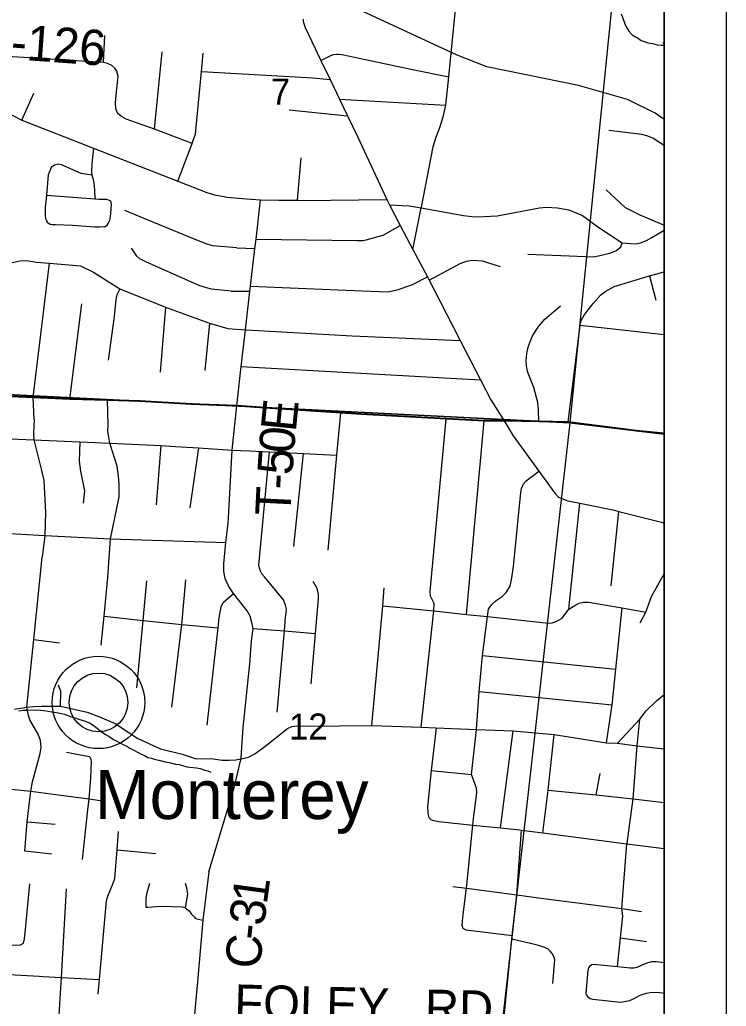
# Model space of a CAD drawing. Extents: x 0 to 43.4, y -8.1 to 22.
# Drawn here: x 7.863 to 9, y 16.255 to 17.842 of the extents above; entities that cross this region are included whole.
import ezdxf

# ---------------------------------------------------------------- set-up
doc = ezdxf.new("R2010")
doc.units = 0
for name, color, linetype in [('GM_X_City_Street', 7, 'Continuous'), ('GM_X_Corporation', 7, 'Continuous'), ('GM_X_County_Road', 7, 'Continuous'), ('GM_X_County_Road_Text', 7, 'Continuous'), ('GM_X_Minor_River', 7, 'Continuous'), ('GM_X_Rail_Line', 7, 'Continuous'), ('GM_X_Section_Text', 7, 'Continuous'), ('GM_X_State_Route', 7, 'Continuous'), ('GM_X_Township_Road', 7, 'Continuous'), ('GM_X_Township_Road_Text', 7, 'Continuous'), ('GM_X_Unincorporated', 7, 'Continuous'), ('GM_X_Unincorporated_Location', 7, 'Continuous'), ('GM_X_Unincorporated_Text', 7, 'Continuous'), ('SH_Data', 7, 'Continuous')]:
    doc.layers.add(name, color=color, linetype=linetype)

msp = doc.modelspace()

# ---------------------------------------------------------------- linework, layer by layer
at = {"layer": 'GM_X_City_Street'}
for p, q in [((8.8978, 17.8048), (8.9, 17.8046)), ((8.3349, 17.7485), (8.3626, 17.7457)), ((8.3778, 17.714), (8.549, 17.7043)), ((8.297, 17.6971), (8.3907, 17.6872)), ((8.3101, 17.5513), (8.3161, 17.6194)), ((8.2124, 17.475), (8.2416, 17.4738)), ((8.8763, 17.4296), (8.8869, 17.3908)), ((8.2037, 17.4054), (8.2337, 17.4052)), ((8.7652, 17.3507), (8.9, 17.3355)), ((8.2197, 17.2841), (8.6047, 17.2626)), ((8.5819, 16.8853), (8.6105, 17.1967)), ((8.0902, 17.1567), (8.0827, 17.0615)), ((8.3041, 16.9943), (8.3196, 17.1438)), ((8.7465, 16.8937), (8.7646, 17.0639)), ((8.8147, 16.9312), (8.8269, 17.0509)), ((8.6079, 16.8193), (8.8222, 16.7971)), ((8.6025, 16.7611), (8.8164, 16.7397)), ((8.5253, 16.6339), (8.5903, 16.6275)), ((8.7905, 16.5952), (8.797, 16.6291)), ((8.8296, 16.3648), (8.8715, 16.3588))]:
    msp.add_line(p, q, dxfattribs=at)
for points in [[(8.3479, 17.7763), (8.3638, 17.784), (8.3683, 17.7859), (8.3727, 17.7864), (8.3763, 17.7866), (8.3813, 17.7858), (8.4119, 17.7796), (8.4953, 17.7619), (8.5535, 17.7498)], [(8.9, 17.6392), (8.8928, 17.6443), (8.882, 17.6511), (8.8723, 17.655), (8.864, 17.6573), (8.8109, 17.6634)], [(8.8067, 17.5683), (8.8376, 17.5396), (8.861, 17.5282), (8.9, 17.5115)], [(8.4582, 17.544), (8.4897, 17.5425), (8.5091, 17.539), (8.5773, 17.5267), (8.5954, 17.5246), (8.6098, 17.5252), (8.6315, 17.5264), (8.6997, 17.5394), (8.711, 17.5403), (8.7283, 17.5391), (8.7467, 17.5359), (8.7685, 17.5267), (8.7949, 17.5076), (8.8324, 17.4828)], [(8.2434, 17.4886), (8.4064, 17.4865), (8.4158, 17.4866), (8.4206, 17.4875), (8.4338, 17.4913), (8.4479, 17.495), (8.4756, 17.5108)], [(8.6809, 17.4647), (8.7869, 17.4605), (8.8038, 17.464), (8.8142, 17.467), (8.8235, 17.4708), (8.8302, 17.4767), (8.8324, 17.4828), (8.8464, 17.482), (8.8545, 17.4815), (8.8621, 17.4827), (8.8718, 17.4869), (8.8801, 17.4915), (8.9, 17.5031)], [(8.5219, 17.4227), (8.5717, 17.4497), (8.5821, 17.4536), (8.5918, 17.4551), (8.6071, 17.4537), (8.6362, 17.445)], [(8.2346, 17.413), (8.4138, 17.4057), (8.4556, 17.404), (8.4705, 17.4073), (8.4939, 17.4153), (8.5191, 17.4282)], [(8.7457, 17.1943), (8.7652, 17.3507), (8.7665, 17.3577), (8.7713, 17.3665), (8.7776, 17.3753), (8.7859, 17.3853), (8.7983, 17.3993), (8.8062, 17.4051), (8.8196, 17.4124), (8.8763, 17.4296), (8.9, 17.4364)], [(8.6984, 17.1954), (8.6981, 17.2135), (8.6969, 17.2262), (8.6903, 17.2501), (8.6803, 17.2759), (8.6788, 17.2848), (8.6783, 17.2929), (8.6787, 17.3002), (8.6796, 17.3084), (8.6819, 17.3168), (8.6852, 17.3253), (8.6885, 17.3333), (8.6987, 17.3491), (8.7081, 17.3599), (8.7331, 17.3813)], [(8.1979, 17.3449), (8.2265, 17.3432), (8.2283, 17.3431), (8.3983, 17.3331), (8.5721, 17.326)], [(8.3596, 16.9884), (8.3736, 17.1411), (8.3798, 17.2094)], [(7.8867, 17.1991), (7.8855, 17.1757), (7.8862, 17.1659), (7.8925, 17.1405), (7.8983, 17.1165), (7.9021, 17.1005), (7.9045, 17.0496), (7.9034, 17.012), (7.8996, 16.9771)], [(7.9944, 16.8359), (7.9991, 16.8821), (8.005, 16.9445), (8.0093, 17.0069), (8.023, 17.0744), (8.0232, 17.0874), (8.0232, 17.0951), (8.0222, 17.1073), (8.0198, 17.1236), (8.0085, 17.1604), (8.0059, 17.1734), (8.005, 17.1794), (8.0053, 17.1899)], [(8.5091, 16.7036), (8.5295, 16.8907), (8.5298, 16.9028), (8.5242, 16.9144), (8.5235, 16.9218), (8.5491, 17.2)], [(7.7363, 17.1725), (7.7606, 17.1712), (7.8358, 17.1679), (7.8862, 17.1659), (7.9601, 17.1629), (8.0085, 17.1604), (8.0902, 17.1567), (8.1141, 17.1554)], [(7.9601, 17.1629), (7.9588, 17.1315), (7.9612, 17.1154), (7.9674, 17.084), (7.9655, 17.0641)], [(8.2332, 17.1481), (8.2651, 17.1465), (8.3196, 17.1438), (8.3736, 17.1411)], [(8.2776, 16.728), (8.289, 16.8589), (8.2909, 16.8809), (8.2919, 16.8871), (8.2922, 16.8935), (8.2908, 16.9), (8.2877, 16.9087), (8.257, 16.9454), (8.253, 16.9503), (8.2508, 16.9545), (8.2489, 16.9594), (8.248, 16.9646), (8.2651, 17.1465)], [(7.7811, 17.0191), (7.9034, 17.012), (8.0093, 17.0069), (8.1949, 17.0006)], [(8.8614, 16.8716), (8.8705, 16.889), (8.8798, 16.9142), (8.9, 16.9503)], [(8.0515, 16.7672), (8.0621, 16.8754), (8.068, 16.9392)], [(8.1078, 16.736), (8.1242, 16.8691), (8.1306, 16.9406)], [(8.332, 16.7733), (8.3393, 16.8546), (8.3442, 16.9101), (8.344, 16.9175), (8.3417, 16.9271), (8.3356, 16.938)], [(8.1646, 16.7068), (8.1827, 16.8637), (8.1843, 16.8799), (8.1871, 16.8971), (8.1908, 16.9046), (8.2073, 16.9189)], [(8.4299, 16.7063), (8.4474, 16.8992), (8.4495, 16.928)], [(8.6161, 16.882), (8.7139, 16.8711), (8.72, 16.8718), (8.7262, 16.8738), (8.7359, 16.8791), (8.7465, 16.8937), (8.7565, 16.8996), (8.7633, 16.9034), (8.7705, 16.9051), (8.7786, 16.9048), (8.8323, 16.8956), (8.8705, 16.889)], [(8.4474, 16.8992), (8.5295, 16.8907), (8.5819, 16.8853), (8.6161, 16.882)], [(8.8072, 16.6788), (8.8164, 16.7397), (8.8222, 16.7971), (8.8323, 16.8956)], [(7.9991, 16.8821), (8.0621, 16.8754), (8.1242, 16.8691), (8.1827, 16.8637)], [(8.2387, 16.8627), (8.289, 16.8589), (8.3393, 16.8546)], [(8.8249, 16.319), (8.8296, 16.3648), (8.8338, 16.3998), (8.8322, 16.4122), (8.8402, 16.5161), (8.8403, 16.5171), (8.8501, 16.5885), (8.8565, 16.6737), (8.8609, 16.7168)], [(8.637, 16.5417), (8.6404, 16.5708), (8.6571, 16.6978)], [(8.7049, 16.5337), (8.7136, 16.6024), (8.723, 16.692)], [(8.825, 16.6778), (8.8565, 16.6737), (8.9, 16.6689)], [(8.7136, 16.6024), (8.7905, 16.5952), (8.8501, 16.5885), (8.9, 16.5826)], [(8.6555, 16.3679), (8.5814, 16.3772), (8.5766, 16.38), (8.575, 16.3848), (8.5764, 16.3984), (8.5822, 16.4446), (8.592, 16.5463)], [(8.5603, 16.4476), (8.5822, 16.4446), (8.663, 16.4343), (8.7062, 16.4284), (8.8322, 16.4122), (8.8636, 16.4072)], [(8.7207, 16.2916), (8.724, 16.3297), (8.7226, 16.3351), (8.72, 16.3398), (8.7167, 16.3436), (8.7134, 16.3466), (8.7079, 16.3495), (8.7019, 16.3513), (8.694, 16.3535), (8.6551, 16.3629)], [(8.7753, 16.2728), (8.7745, 16.2761), (8.7777, 16.3131), (8.7788, 16.3168), (8.7799, 16.3185), (8.7815, 16.3204), (8.7838, 16.3218), (8.7862, 16.3225), (8.8249, 16.319), (8.8454, 16.3165), (8.8512, 16.3169), (8.8567, 16.3179), (8.8683, 16.323), (8.8745, 16.3254), (8.88, 16.3266), (8.8873, 16.327), (8.9, 16.3251)], [(8.7753, 16.2728), (8.7775, 16.27), (8.7808, 16.2675), (8.7851, 16.2664), (8.8299, 16.2616), (8.8387, 16.2629), (8.8443, 16.2643), (8.8519, 16.2674), (8.8606, 16.2721), (8.8662, 16.2742), (8.8716, 16.2758), (8.8777, 16.2772), (8.8876, 16.2777), (8.8972, 16.2766), (8.9, 16.2761)]]:
    msp.add_lwpolyline(points, dxfattribs=at)
at = {"layer": 'GM_X_Corporation'}
for points in [[(8.9, 14.3814), (8.9, 20.9), (2.1, 20.9)], [(7.7999, 17.2384), (7.8847, 17.2346), (7.9436, 17.232), (8.0041, 17.2301), (8.0564, 17.2286), (8.139, 17.2237), (8.2121, 17.2213), (8.3796, 17.21), (8.4125, 17.2077), (8.5489, 17.2005), (8.6103, 17.1972), (8.6426, 17.1973), (8.6981, 17.1959), (8.7454, 17.1948), (8.8548, 17.1812), (8.9, 17.1765), (8.9, 20.9)], [(8.9, 14.3814), (8.9, 17.1765), (8.8548, 17.1812), (8.7454, 17.1948), (8.6981, 17.1959), (8.6426, 17.1973), (8.6103, 17.1972), (8.5489, 17.2005), (8.4125, 17.2077), (8.3796, 17.21), (8.2121, 17.2213), (8.139, 17.2237), (8.0564, 17.2286), (8.0041, 17.2301), (7.9436, 17.232), (7.8847, 17.2346), (7.7999, 17.2384)]]:
    msp.add_lwpolyline(points, dxfattribs=at)
for points in [[(8.8482, 18.1867), (8.7485, 17.1931), (7.7575, 17.2431), (7.8526, 18.2674)], [(8.9, 17.1752), (8.9, 18.1813), (8.8482, 18.1867), (8.7485, 17.1931)], [(7.7575, 17.2431), (8.7485, 17.1931), (8.6363, 16.199), (7.6501, 16.228)], [(8.9, 16.1667), (8.9, 17.1752), (8.7485, 17.1931), (8.6363, 16.199)]]:
    msp.add_lwpolyline(points, close=True, dxfattribs=at)
at = {"layer": 'GM_X_County_Road'}
for p, q in [((8.2507, 17.5519), (8.2804, 17.5516)), ((8.4959, 17.4722), (8.5091, 17.539)), ((8.1491, 16.294), (8.1419, 16.2128))]:
    msp.add_line(p, q, dxfattribs=at)
for points in [[(8.5091, 17.539), (8.5094, 17.5405), (8.5284, 17.6371), (8.5329, 17.6519), (8.5389, 17.6682), (8.5445, 17.6856), (8.549, 17.7043), (8.5535, 17.7498), (8.5802, 18.0214), (8.5891, 18.1119), (8.5951, 18.1657), (8.6156, 18.3483)], [(7.6994, 17.7637), (7.7646, 17.7326), (7.8665, 17.6802), (7.9818, 17.6351), (8.1177, 17.5819), (8.1642, 17.5637), (8.1766, 17.56), (8.1924, 17.5572)], [(8.1924, 17.5572), (8.1944, 17.5568), (8.1966, 17.5564), (8.2282, 17.5538), (8.2507, 17.5519)], [(8.2804, 17.5516), (8.3101, 17.5513), (8.3179, 17.5512), (8.4537, 17.5525)], [(6.2065, 17.4049), (6.4191, 17.3852), (6.5024, 17.3775), (6.7305, 17.3523), (6.8403, 17.3405), (6.934, 17.3317), (7.0194, 17.3221), (7.1459, 17.3085), (7.2379, 17.2981), (7.3491, 17.2862), (7.3995, 17.281), (7.6127, 17.2515), (7.6512, 17.2473), (7.707, 17.2463), (7.7489, 17.2401), (7.8001, 17.2378), (7.885, 17.2341), (7.9438, 17.2315), (8.0044, 17.2296), (8.0566, 17.228), (8.1392, 17.2232), (8.1943, 17.2214)], [(8.1943, 17.2214), (8.2123, 17.2208), (8.2419, 17.2188)], [(8.2419, 17.2188), (8.3798, 17.2094), (8.4127, 17.2072), (8.5491, 17.2), (8.6105, 17.1967), (8.6429, 17.1968)], [(8.6429, 17.1968), (8.6984, 17.1954), (8.7362, 17.1945)], [(8.7362, 17.1945), (8.7457, 17.1943), (8.855, 17.1807), (8.9, 17.176)], [(8.592, 16.5463), (8.5933, 16.5569), (8.5985, 16.5984), (8.5979, 16.6056), (8.5903, 16.6275), (8.5981, 16.6999), (8.6025, 16.7611), (8.6079, 16.8193), (8.6161, 16.882), (8.6177, 16.8937), (8.6222, 16.9004), (8.6298, 16.9074), (8.6392, 16.9139), (8.6461, 16.9206), (8.6523, 16.9307), (8.655, 16.9439), (8.6575, 16.962), (8.6695, 17.0814), (8.6705, 17.0877), (8.6738, 17.0953), (8.6782, 17.1), (8.6984, 17.1157)], [(8.1901, 16.6506), (8.2002, 16.6506), (8.2112, 16.6515), (8.2196, 16.6531), (8.2311, 16.6556), (8.2415, 16.6611), (8.2574, 16.6725), (8.2941, 16.7016), (8.301, 16.7048), (8.3087, 16.7062), (8.3249, 16.7053), (8.4299, 16.7063), (8.5091, 16.7036), (8.5335, 16.7025), (8.5981, 16.6999), (8.6571, 16.6978), (8.723, 16.692), (8.8072, 16.6788), (8.825, 16.6778), (8.8609, 16.7168), (8.8709, 16.7302), (8.8875, 16.7461), (8.9, 16.7565)], [(7.8546, 16.7325), (7.8749, 16.7361), (7.8859, 16.7369), (7.898, 16.7378), (7.9286, 16.7377), (7.972, 16.7277), (7.9918, 16.7202), (8.017, 16.7095), (8.0534, 16.6858), (8.0899, 16.6692), (8.1245, 16.6605), (8.1471, 16.6528), (8.1711, 16.6532), (8.1891, 16.6506), (8.1901, 16.6506)], [(8.5335, 16.7025), (8.5253, 16.6339), (8.5195, 16.5756), (8.5199, 16.567), (8.5201, 16.5659)], [(8.5201, 16.5659), (8.5205, 16.5628), (8.5217, 16.5586), (8.5234, 16.5566), (8.5247, 16.5554), (8.5271, 16.5543), (8.5295, 16.5535), (8.5321, 16.5529), (8.5375, 16.552), (8.592, 16.5463), (8.637, 16.5417), (8.6679, 16.5385), (8.6708, 16.5382)], [(8.639, 16.2005), (8.6551, 16.3629), (8.6555, 16.3679), (8.663, 16.4343), (8.6708, 16.5382)], [(8.6708, 16.5382), (8.7049, 16.5337), (8.8402, 16.5161), (8.9, 16.5084)], [(8.1673, 16.4711), (8.158, 16.3932), (8.1491, 16.294)]]:
    msp.add_lwpolyline(points, dxfattribs=at)
at = {"layer": 'GM_X_Minor_River'}
for points in [[(8.8309, 17.8513), (8.8331, 17.8459), (8.8373, 17.8336), (8.8402, 17.8289), (8.8435, 17.8235), (8.8483, 17.818), (8.8528, 17.8148), (8.8573, 17.8124), (8.8629, 17.8085), (8.8693, 17.8064), (8.8738, 17.8047), (8.8814, 17.8034), (8.8889, 17.8016), (8.8954, 17.8007), (8.9, 17.8006)], [(7.862, 16.73), (7.8688, 16.7309), (7.8738, 16.7312), (7.8883, 16.7315), (7.8974, 16.7309), (7.9057, 16.7299), (7.9148, 16.7285), (7.9258, 16.7267), (7.9345, 16.7245), (7.9394, 16.7229), (7.9476, 16.72), (7.9522, 16.7187), (7.9567, 16.717), (7.9684, 16.7137), (7.9755, 16.7108), (7.9815, 16.7072), (7.9879, 16.7021), (7.9945, 16.6966), (8.0013, 16.6918), (8.0069, 16.6886), (8.014, 16.6838), (8.0207, 16.6806), (8.0252, 16.6778), (8.0305, 16.6754), (8.0354, 16.673), (8.0402, 16.6698), (8.0459, 16.6673), (8.0519, 16.6641), (8.059, 16.6601), (8.0642, 16.6581), (8.0695, 16.6552), (8.0752, 16.6539), (8.0816, 16.6519), (8.0872, 16.6506), (8.0971, 16.648), (8.1039, 16.6467), (8.1141, 16.6445), (8.1198, 16.6439), (8.125, 16.6423), (8.1322, 16.6402), (8.1371, 16.6393), (8.1424, 16.6391), (8.1477, 16.6382), (8.1538, 16.6373), (8.1613, 16.6348), (8.1659, 16.6335), (8.1708, 16.6315)]]:
    msp.add_lwpolyline(points, dxfattribs=at)
at = {"layer": 'GM_X_Rail_Line'}
msp.add_lwpolyline([(8.9, 17.6811), (8.8855, 17.6915), (8.8412, 17.7137), (8.762, 17.7358), (8.6148, 17.7659), (8.5673, 17.785), (8.3852, 17.869)], dxfattribs=at)
at = {"layer": 'GM_X_State_Route'}
for points in [[(8.3195, 17.8426), (8.3192, 17.8388), (8.3225, 17.8291), (8.3387, 17.7953)], [(8.3387, 17.7953), (8.3419, 17.7887), (8.3479, 17.7763), (8.3626, 17.7457), (8.3778, 17.714), (8.3907, 17.6872), (8.4066, 17.6542), (8.4537, 17.5525), (8.4582, 17.544), (8.4756, 17.5108), (8.4959, 17.4722), (8.5191, 17.4282), (8.5219, 17.4227), (8.5398, 17.3887), (8.5721, 17.326), (8.6047, 17.2626), (8.6213, 17.2302), (8.6429, 17.1968), (8.657, 17.1724), (8.6984, 17.1157), (8.7243, 17.0802), (8.7299, 17.0737), (8.7451, 17.0678), (8.7646, 17.0639), (8.7749, 17.0618)], [(8.7749, 17.0618), (8.8203, 17.0526), (8.8269, 17.0509), (8.8957, 17.0333), (8.9, 17.0319)]]:
    msp.add_lwpolyline(points, dxfattribs=at)
at = {"layer": 'GM_X_Township_Road'}
for p, q in [((7.9981, 17.7728), (8.0003, 17.8165)), ((8.0803, 17.6655), (8.0926, 17.7903)), ((8.1557, 17.7586), (8.3349, 17.7485)), ((7.8665, 17.6802), (7.8862, 17.7237)), ((8.0789, 17.5158), (8.0326, 17.5347)), ((7.9438, 17.2315), (7.9633, 17.3847)), ((8.098, 17.3795), (8.089, 17.2749)), ((8.1686, 17.3535), (8.1609, 17.2776)), ((7.8867, 17.1991), (7.885, 17.2341)), ((8.0053, 17.1899), (8.0044, 17.2296)), ((8.151, 17.1531), (8.1372, 17.0564)), ((8.205, 17.1492), (8.2332, 17.1481)), ((7.886, 16.8446), (7.9272, 16.8394)), ((7.8753, 16.5515), (7.9201, 16.5477)), ((8.0198, 16.5067), (8.0824, 16.5008))]:
    msp.add_line(p, q, dxfattribs=at)
for points in [[(8.1406, 17.6429), (8.0803, 17.6655), (8.0346, 17.6817), (8.027, 17.6862), (8.0213, 17.6911), (8.018, 17.6987), (8.0173, 17.7086), (8.0182, 17.7204), (8.0215, 17.751), (8.0197, 17.7588), (8.0164, 17.7637), (8.0115, 17.7683), (8.0043, 17.7716), (7.9981, 17.7728), (7.8002, 17.7851), (7.7918, 17.7827), (7.7856, 17.7784), (7.7814, 17.7708), (7.7646, 17.7326), (7.7473, 17.6986), (7.7459, 17.6893), (7.7482, 17.6409), (7.7521, 17.5288)], [(8.1177, 17.5819), (8.1406, 17.6429), (8.1418, 17.6462), (8.1441, 17.6518), (8.1462, 17.6579), (8.1557, 17.7586), (8.1584, 17.7879)], [(7.9818, 17.6351), (7.9791, 17.6101), (7.9785, 17.5971), (7.9791, 17.5919), (7.9806, 17.5884), (7.9816, 17.585), (7.9826, 17.5789), (7.9837, 17.5683), (7.9841, 17.5536)], [(7.9791, 17.5919), (7.9619, 17.5946), (7.9306, 17.6086), (7.9254, 17.6092), (7.9191, 17.608), (7.9139, 17.6042), (7.9116, 17.5986), (7.9088, 17.5922), (7.9064, 17.5597), (7.9043, 17.5395), (7.904, 17.5323), (7.9044, 17.5275), (7.9048, 17.5218), (7.9061, 17.5187), (7.9074, 17.5163), (7.9103, 17.514)], [(7.9064, 17.5597), (7.9841, 17.5536), (7.9909, 17.5533), (7.997, 17.5533), (8.0009, 17.553), (8.0027, 17.5529), (8.0058, 17.5519), (8.0092, 17.5503)], [(8.2123, 17.2208), (8.2197, 17.2841), (8.2265, 17.3432), (8.2337, 17.4052), (8.2346, 17.413), (8.2416, 17.4738), (8.2434, 17.4886), (8.2507, 17.5519)], [(8.0092, 17.5503), (8.0105, 17.5445), (8.0093, 17.5304), (8.0088, 17.525), (8.0077, 17.5189), (8.0055, 17.5143), (8.0031, 17.5105), (8.0002, 17.5083), (7.9963, 17.5084), (7.9914, 17.5081), (7.9836, 17.5082)], [(7.9836, 17.5082), (7.9482, 17.5107), (7.9209, 17.5116), (7.9156, 17.512), (7.9123, 17.5125), (7.9103, 17.514)], [(8.2124, 17.475), (8.1734, 17.4783), (8.1633, 17.4812), (8.1483, 17.4873), (8.0789, 17.5158)], [(8.2037, 17.4054), (8.1719, 17.4081), (8.1637, 17.4103), (8.1532, 17.4136), (8.067, 17.452), (8.0563, 17.457), (8.0515, 17.4616), (8.0431, 17.4742)], [(7.8275, 17.4439), (7.8488, 17.4508), (7.8635, 17.4537), (7.874, 17.4547), (7.8902, 17.4519), (7.9114, 17.4501), (7.9611, 17.4457), (7.9817, 17.4356), (8.0242, 17.409), (8.098, 17.3795), (8.1686, 17.3535), (8.1979, 17.3449)], [(7.885, 17.2341), (7.8887, 17.2654), (7.9114, 17.4501)], [(8.0242, 17.409), (8.0195, 17.3991), (8.0177, 17.3919), (8.0153, 17.3645), (8.0053, 17.2942)], [(8.1984, 17.0322), (8.1993, 17.0406), (8.205, 17.1492), (8.2123, 17.2208)], [(8.1141, 17.1554), (8.151, 17.1531), (8.205, 17.1492)], [(8.2073, 16.9189), (8.1997, 16.9301), (8.194, 16.9429), (8.1916, 16.9542), (8.1917, 16.9663), (8.1949, 17.0006), (8.1984, 17.0322)], [(7.8749, 16.7361), (7.886, 16.8446), (7.8996, 16.9771)], [(8.2202, 16.6631), (8.2225, 16.7033), (8.2336, 16.8058), (8.2364, 16.8427), (8.2387, 16.8627), (8.236, 16.8742), (8.2338, 16.8821), (8.2294, 16.8912), (8.2073, 16.9189)], [(7.9286, 16.7377), (7.9293, 16.761), (7.9259, 16.7712)], [(7.9151, 16.4993), (7.8717, 16.5046), (7.8753, 16.5515), (7.8811, 16.6007), (7.8837, 16.616), (7.8964, 16.6614), (7.8977, 16.6712), (7.8967, 16.6825), (7.8929, 16.6926), (7.8796, 16.7157), (7.8774, 16.7224), (7.8749, 16.7361)], [(7.9645, 16.4907), (7.9731, 16.5706), (7.9748, 16.5883), (7.9779, 16.6217), (7.9785, 16.6498), (7.9782, 16.6516), (7.9774, 16.6542), (7.9763, 16.6556), (7.9754, 16.6563), (7.9384, 16.663)], [(8.1673, 16.4711), (8.2086, 16.6086), (8.2181, 16.6473), (8.2196, 16.6531), (8.2202, 16.6631)], [(7.8493, 16.6038), (7.8811, 16.6007), (7.9296, 16.5943), (7.9748, 16.5883), (7.9997, 16.585)], [(7.9895, 16.2741), (7.9916, 16.2979), (8.003, 16.4244), (8.0051, 16.4319), (8.0136, 16.4526), (8.0161, 16.4605), (8.0198, 16.5067), (8.0223, 16.5362)], [(7.8329, 16.4547), (7.8214, 16.3546), (7.8168, 16.3151), (7.8179, 16.3117), (7.8212, 16.3086), (7.8265, 16.3069), (7.8945, 16.3032), (7.9004, 16.3029)], [(7.8214, 16.3546), (7.853, 16.3531), (7.8644, 16.3539), (7.8696, 16.3565), (7.8707, 16.3632), (7.872, 16.3732), (7.8793, 16.4516)], [(7.9253, 16.2153), (7.9303, 16.3012), (7.9386, 16.4436)], [(8.0722, 16.4525), (8.0677, 16.4375), (8.0662, 16.4292), (8.0662, 16.4142), (8.0692, 16.4142), (8.091, 16.4157), (8.1248, 16.4149), (8.1274, 16.4142), (8.1299, 16.413), (8.1318, 16.4118), (8.1357, 16.4086), (8.1398, 16.4028), (8.1442, 16.3981), (8.1456, 16.3964), (8.1481, 16.3954), (8.158, 16.3932)], [(8.1299, 16.413), (8.1338, 16.4352), (8.1323, 16.445), (8.1301, 16.4525)], [(7.9004, 16.3029), (7.9303, 16.3012), (7.9916, 16.2979)]]:
    msp.add_lwpolyline(points, dxfattribs=at)
at = {"layer": 'GM_X_Unincorporated'}
for radius in [0.0744, 0.0472]:
    msp.add_circle((7.9899, 16.7437), radius, dxfattribs=at)
at = {"layer": 'GM_X_Unincorporated_Location'}
msp.add_line((7.9899, 16.7437), (7.9899, 16.7437), dxfattribs=at)
at = {"layer": 'SH_Data'}
for p, q in [((9, 21), (9, 14)), ((8.9, 20.9), (8.9, 14.1))]:
    msp.add_line(p, q, dxfattribs=at)

# ---------------------------------------------------------------- texts
at = {"layer": 'GM_X_County_Road_Text'}
for s, height, rotation, p in [('C-126', 0.05682, 355.8754, (7.7931, 17.7825)), ('1', 0.0568, 82.2195, (8.2607, 16.4175)), ('3', 0.0568, 83.1235, (8.2565, 16.383)), ('-', 0.0568, 84.0882, (8.2541, 16.36)), ('C', 0.0568, 85.1584, (8.2502, 16.3138)), ('FOLEY', 0.05682, 358.5154, (8.2079, 16.2333)), ('RD', 0.05682, 359.0128, (8.5147, 16.225))]:
    msp.add_text(s, height=height, rotation=rotation, dxfattribs=at).set_placement(p)
at = {"layer": 'GM_X_Section_Text'}
for s, height, p in [('7', 0.0419, (8.2673, 17.7053)), ('12', 0.04186, (8.2964, 16.6839))]:
    msp.add_text(s, height=height, rotation=0, dxfattribs=at).set_placement(p)
at = {"layer": 'GM_X_Township_Road_Text'}
for s, rotation, p in [('E', 84.2303, (8.3073, 17.1776)), ('0', 85.199, (8.3044, 17.143)), ('5', 86.107, (8.302, 17.1083)), ('-', 86.8526, (8.3008, 17.0852)), ('T', 87.15, (8.2987, 17.0428))]:
    msp.add_text(s, height=0.0568, rotation=rotation, dxfattribs=at).set_placement(p)
at = {"layer": 'GM_X_Unincorporated_Text'}
msp.add_text('Monterey', height=0.07898, rotation=0, dxfattribs=at).set_placement((7.9843, 16.556))

doc.saveas('drawing.dxf')
